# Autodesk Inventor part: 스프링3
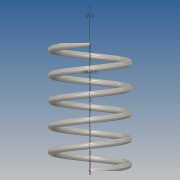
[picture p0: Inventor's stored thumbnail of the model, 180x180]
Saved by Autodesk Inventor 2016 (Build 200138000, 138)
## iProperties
Created: 2016-01
Part Number: 스프링3
Material: 스테인레스 스틸
Document SubType Name: Modeling
Designer: Administrator
Density: 8 g/cm^3
Appearance: 반연마
Mass: 8.55023 g
Surface Area: 21.6678 cm^2
Volume: 1.06878 cm^3
Author: Administrator
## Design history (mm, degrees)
sketch "스케치1"
  geometry: L1 (0, 0)-(11, 0); L2 (11, 0)-(11, 36.411); L3 (11, 36.411)-(0, 36.411); L4 (0, 36.411)-(0, 0); C1 r 1 at (11, 0)
  constraints: 8 end point, 2 parallel, 1 centre point, 1 coincident, 1 horizontal, 1 perpendicular
  dimensions: "d0" = 2 diameter of C1; "d1" = 36.4112 distance of L1.end L2.end (derived); "d2" = 22 diameter of L2 L4
feature "코일1" pitch "d3" = 10; turns "d5" = 5; dims "d4" = 36.4112 (= d1), "d6" = 0, angle "d7" = 90 deg, angle "d8" = 90 deg, "d9" = 0, "d10" = 0
sketch "스케치2"
  geometry: L1 (5.3, 0)-(-21.597, 0); L2 (-21.597, 0)-(-21.597, -10.619); L3 (-21.597, -10.619)-(5.3, -10.619); L4 (5.3, -10.619)-(5.3, 0); 3 further points
  constraints: 8 end point, 2 parallel, 1 horizontal, 1 horizontal alignment, 1 perpendicular, 1 point on line
extrude "돌출1" cut sketch "스케치2" stored distance "d11" = 0; taper "d12" = 0 deg
sketch "스케치3"
  geometry: L1 (-4.261, 0)-(22.454, 0); L2 (22.454, 0)-(22.454, 6.999); L3 (22.454, 6.999)-(-4.261, 6.999); L4 (-4.261, 6.999)-(-4.261, 0); 3 further points
  constraints: 8 end point, 2 parallel, 1 horizontal, 1 horizontal alignment, 1 perpendicular, 1 point on line
extrude "돌출2" cut sketch "스케치3" stored distance "d13" = 0; taper "d14" = 0 deg
node "솔리드1"
